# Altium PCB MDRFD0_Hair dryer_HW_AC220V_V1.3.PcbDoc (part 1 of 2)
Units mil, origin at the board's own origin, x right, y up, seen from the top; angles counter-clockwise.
Board outline 2501.37 x 2501.36 mil, 2 copper layers (Top Layer, Bottom Layer), stack 65.792 mil thick; 130 components, 77 nets, 332 pads, 233 vias.
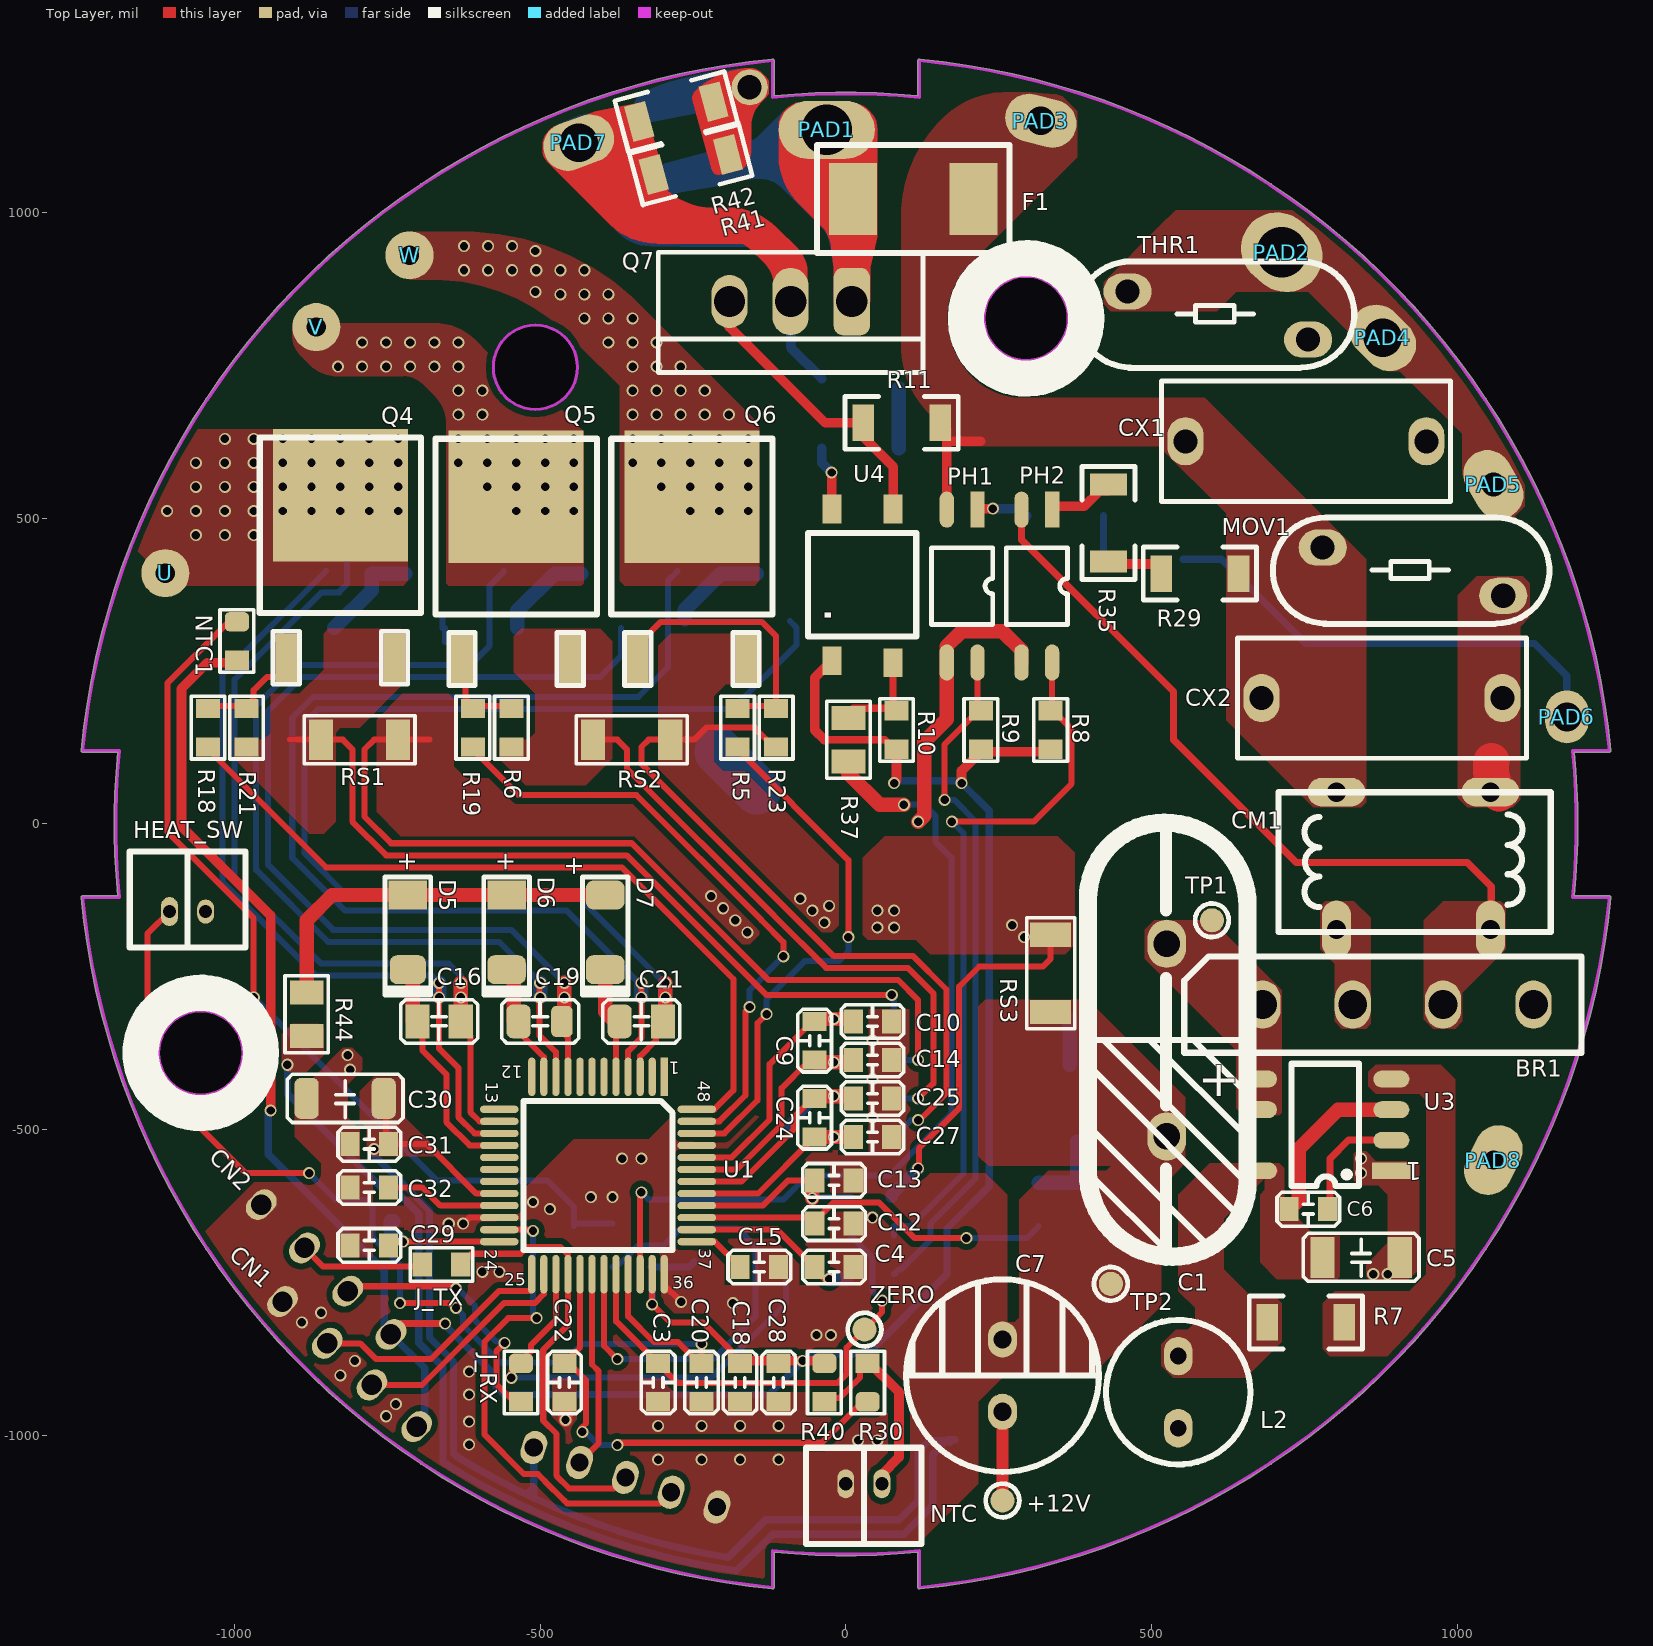
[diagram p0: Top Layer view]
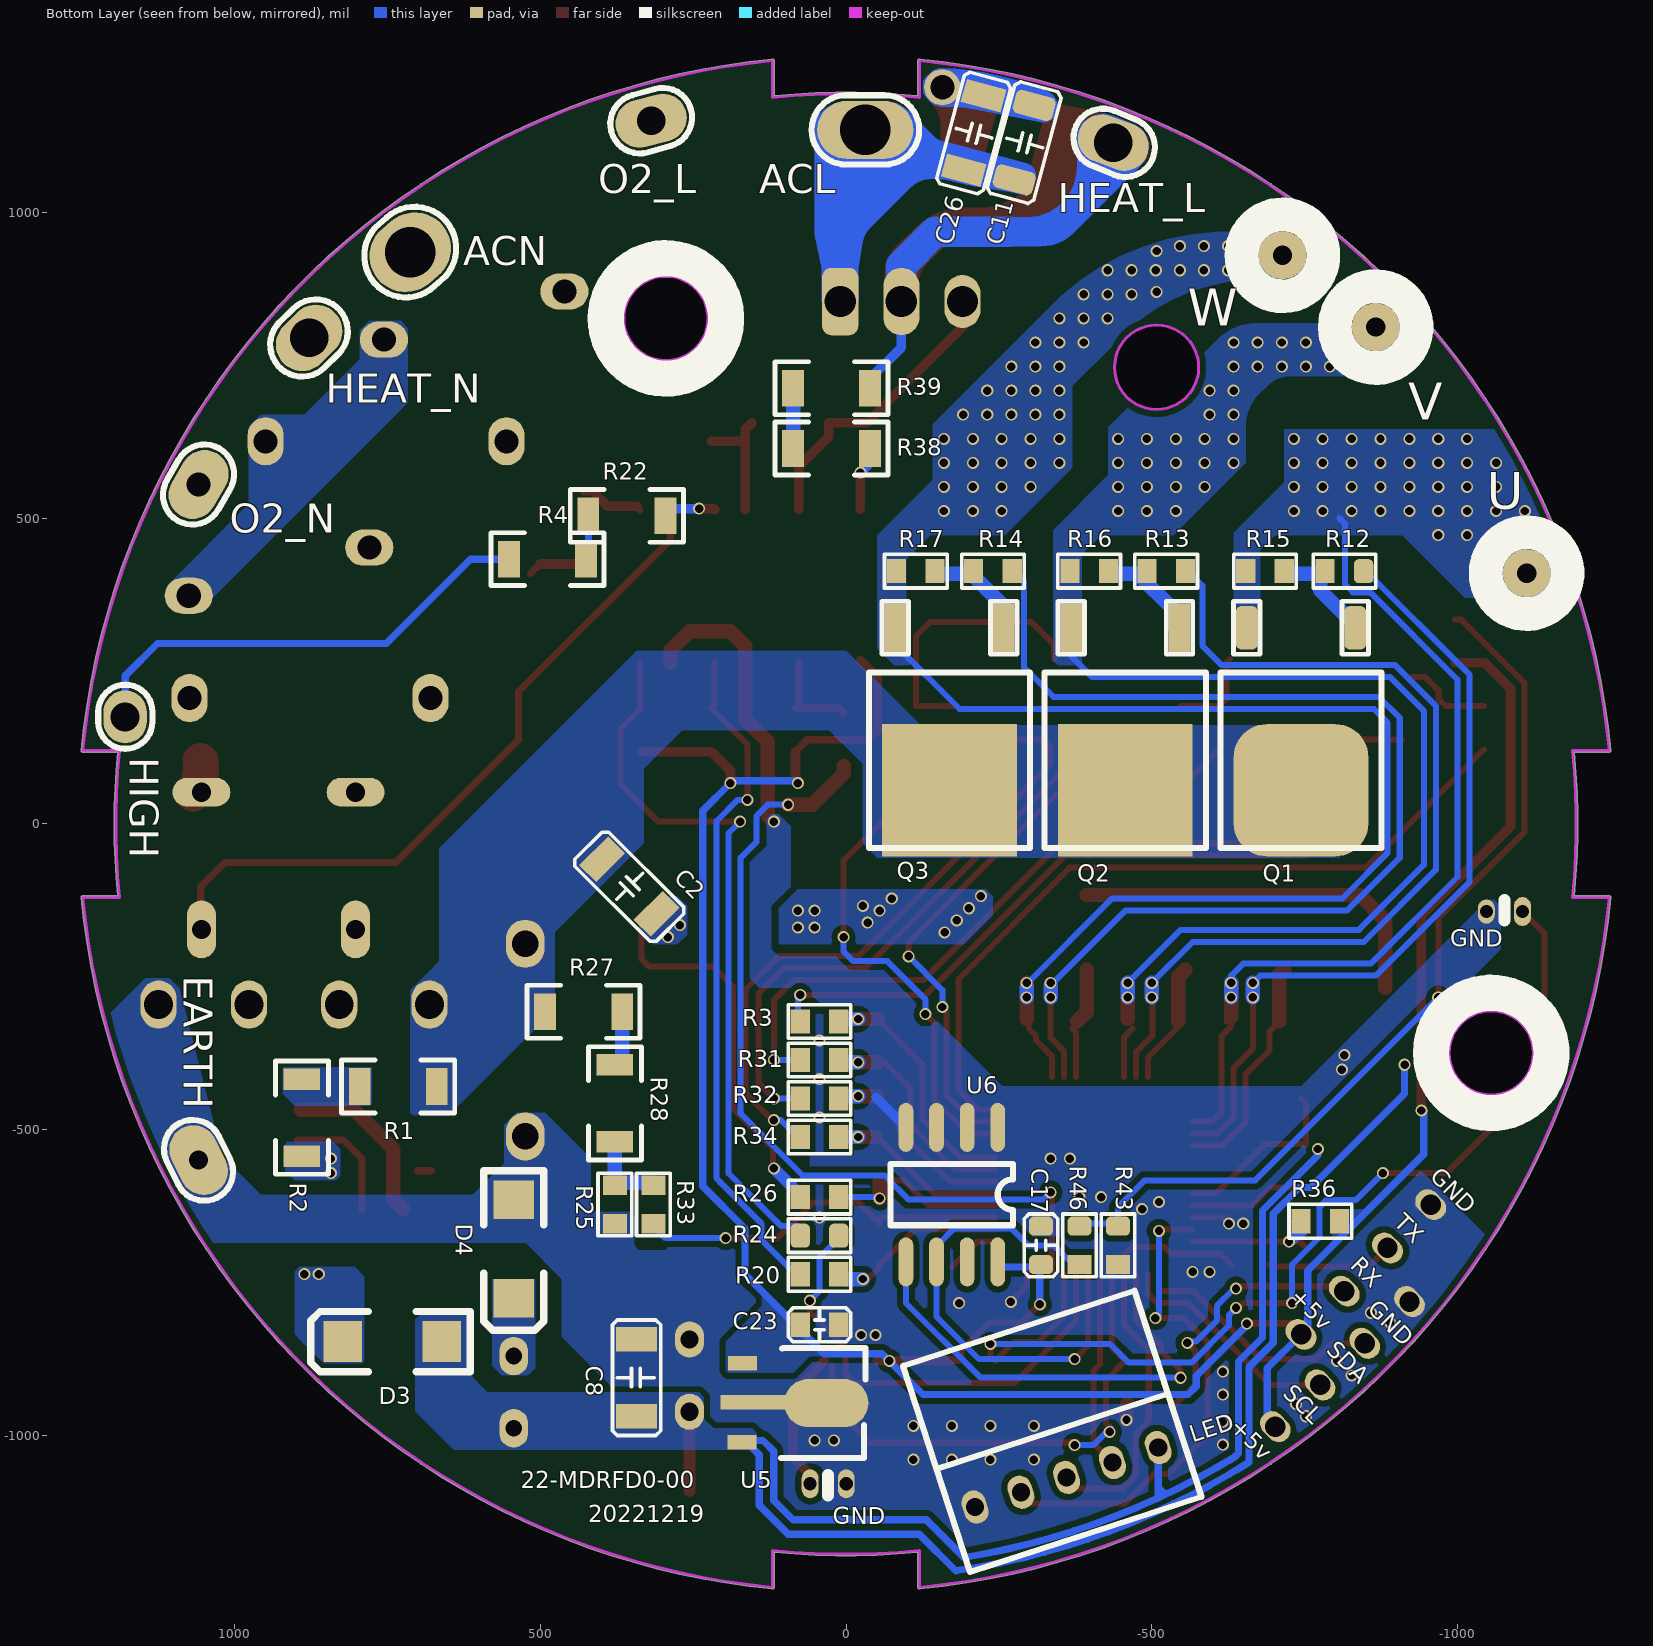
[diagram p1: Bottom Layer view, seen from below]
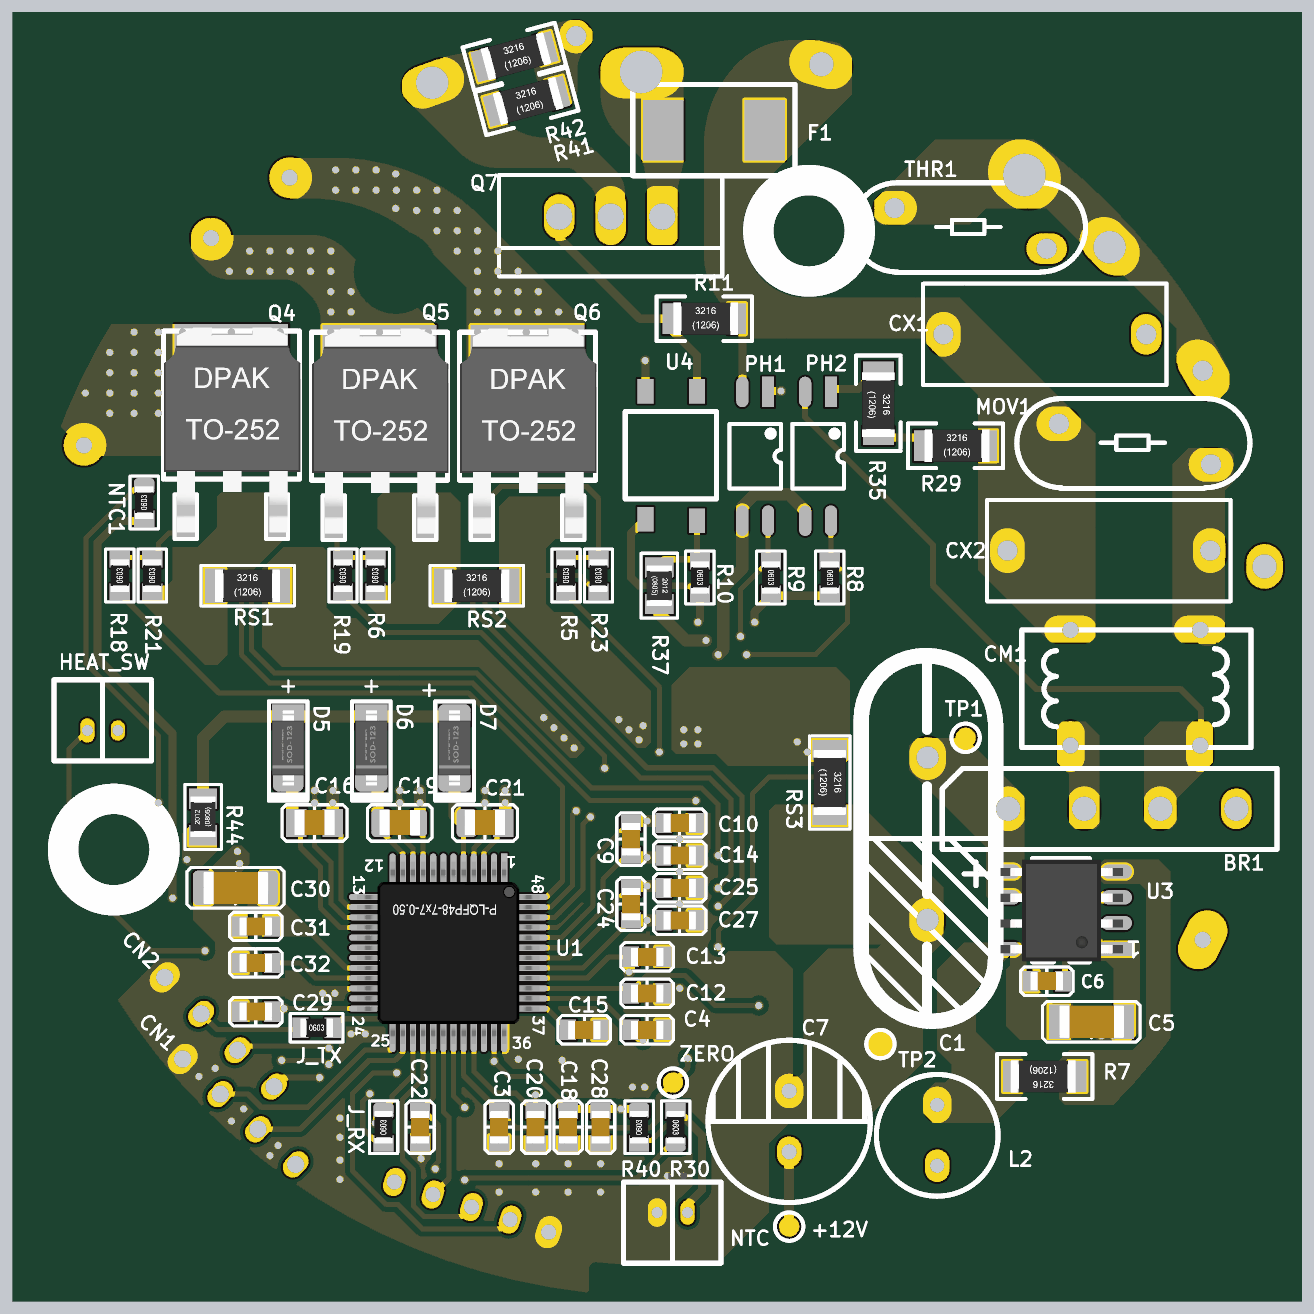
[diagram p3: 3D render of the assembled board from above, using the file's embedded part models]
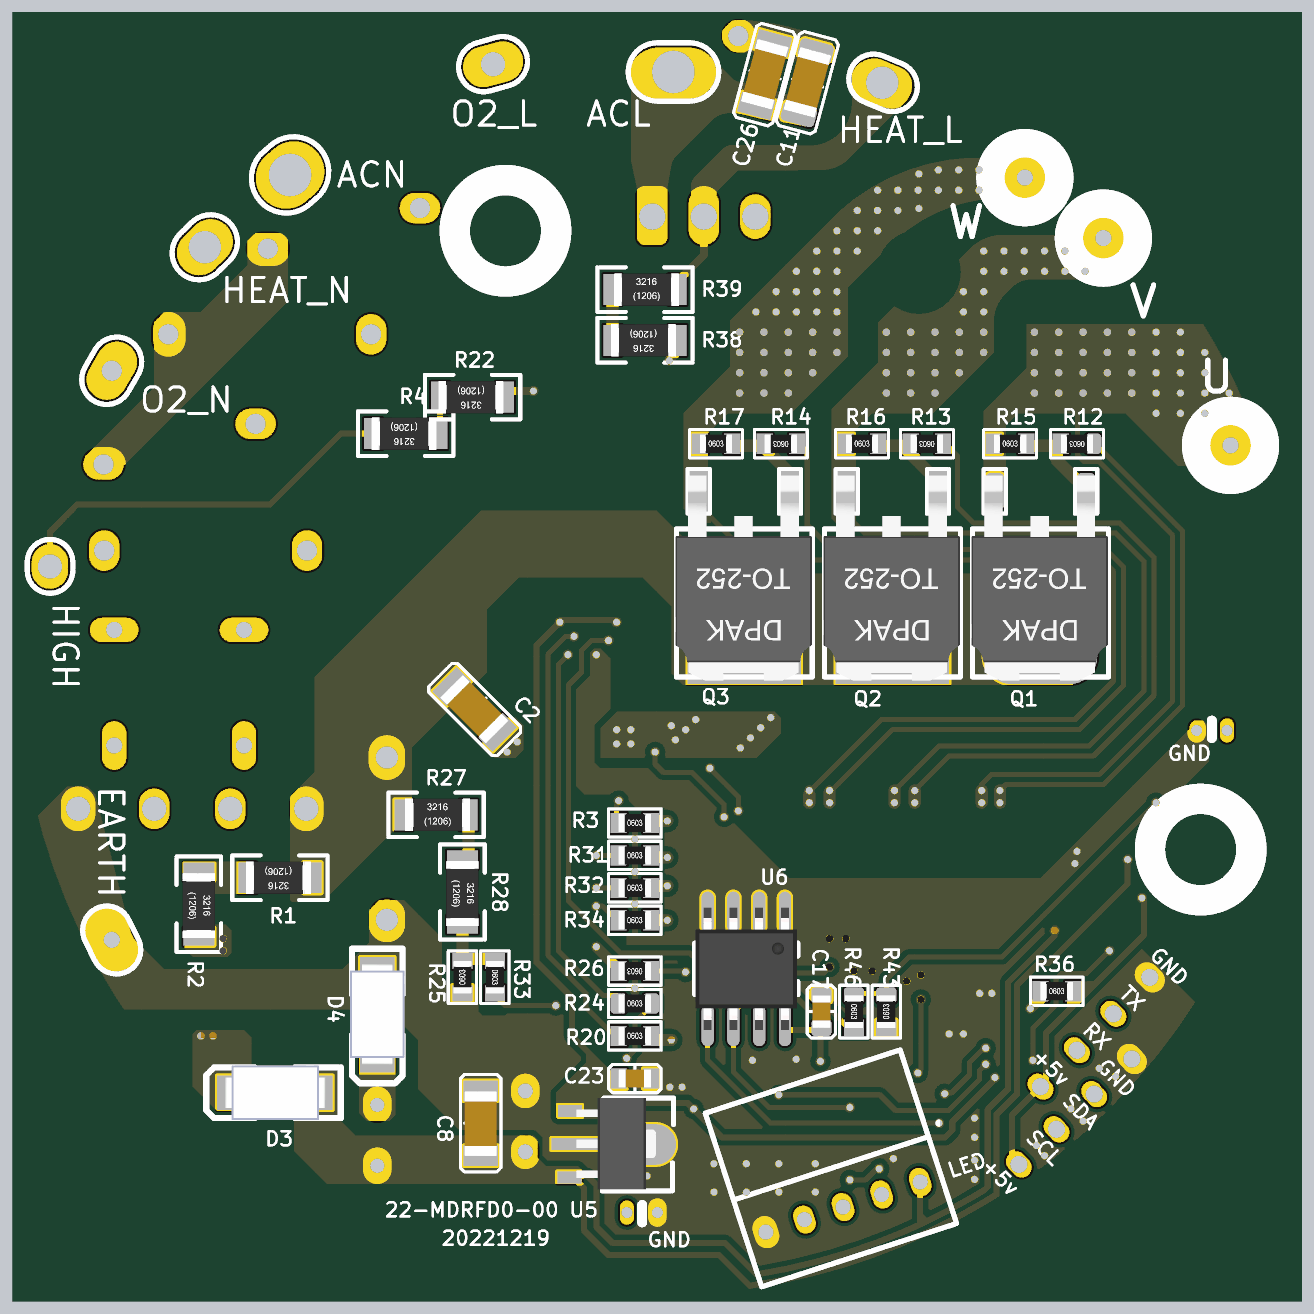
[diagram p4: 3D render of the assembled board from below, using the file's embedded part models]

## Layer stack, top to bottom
Top Solder: solder mask 0.4, Solder Resist, Dk 3.5
Top Layer: signal copper 1.4
Dielectric1: core 62.9921, FR-4, Dk 4.8
Bottom Layer: signal copper 1.4
Bottom Solder: solder mask 0.4, Solder Resist, Dk 3.5

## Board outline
-1250.68,-120.34 cw(c-1248.17,-120.1) -1247.89,-117.6 cw(c-1247.13,-120) -1247.13,-117.48 -1190.78,-117.48 cw(c0,0) -1190.78,117.49 -1247.13,117.49 cw(c-1247.13,120) -1247.87,117.6 cw(c-1248.17,120.1) -1250.68,120.34 cw(c0,0) -120.34,1250.67 cw(c-120.1,1248.17) -117.58,1248.17 cw(c-120.1,1248.17) -117.6,1247.88 cw(c-120,1247.14) -117.49,1247.14 -117.49,1190.78 cw(c0,0) 117.48,1190.78 117.48,1247.14 cw(c120,1247.14) 117.6,1247.88 cw(c120.1,1248.17) 120.34,1250.67 cw(c0,0) 1250.68,120.34 cw(c1248.17,120.1) 1250.69,120.1 cw(c1248.17,120.1) 1247.87,117.6 cw(c1247.13,120) 1247.13,117.49 1190.78,117.49 cw(c0,0) 1196.56,0 cw(c0,0) 1190.78,-117.48 1247.13,-117.48 cw(c1247.13,-120) 1247.89,-117.6 cw(c1248.17,-120.1) 1250.69,-120.1 cw(c1248.17,-120.1) 1250.68,-120.34 cw(c0,0) 120.34,-1250.68 cw(c120.1,-1248.17) 117.6,-1247.88 cw(c120,-1247.13) 117.48,-1247.13 117.48,-1190.78 cw(c0,0) -117.49,-1190.78 -117.49,-1247.13 cw(c-120,-1247.13) -117.6,-1247.88 cw(c-120.1,-1248.17) -117.58,-1248.17 cw(c-120.1,-1248.17) -120.34,-1250.68 cw(c0,0)
cut-out: -1124.02,-374.41 ccw(c-1055.12,-374.41) -1055.12,-443.31 ccw(c-1055.12,-374.41) -986.22,-374.41 ccw(c-1055.12,-374.41) -1055.12,-305.51 ccw(c-1055.12,-374.41)
cut-out: -576.77,746.85 ccw(c-507.87,746.85) -507.87,677.95 ccw(c-507.87,746.85) -438.98,746.85 ccw(c-507.87,746.85) -507.87,815.75 ccw(c-507.87,746.85)
cut-out: 225.59,826.77 ccw(c294.49,826.77) 294.49,757.87 ccw(c294.49,826.77) 363.38,826.77 ccw(c294.49,826.77) 294.49,895.67 ccw(c294.49,826.77)

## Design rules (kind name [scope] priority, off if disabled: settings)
Clearance Clearance_1 [InComponent('U1')] p1: gap=7.87
Clearance [All] p2: gap=9.84
ComponentClearance [All] p1 off: gap=10 collisioncheckmode=3 verticalgap=10 showdistances=FALSE
Height [All] p1 off: minheight=0 maxheight=1000 prefheight=500
HoleSize [All] p1: absolutevalues=TRUE maxlimit=236.22 minlimit=1 maxpercent=80.000 minpercent=20.000
HoleToHoleClearance [All] p1: gap=3.94 allowstackedmicrovias=TRUE
MinimumSolderMaskSliver [All] p1: minsoldermaskwidth=0
PolygonConnect [All] p1: connectstyle=Direct reliefconductorwidth=10 reliefentries=4 polygonreliefangle="90 Angle" airgapwidth=10
RoutingVias [All] p1: holewidth=28 width=50 viastyle="Through Hole" minholewidth=13.78 minwidth=19.68 maxholewidth=28 maxwidth=50
SilkToSilkClearance [All] p1: silktosilkclearance=0.39
SilkToSolderMaskClearance [IsPad] p1: minsilkscreentomaskgap=0 clearancetoexposedcopper=TRUE
SolderMaskExpansion SolderMaskExpansion_1 [IsVia] p1: expansion=-196.85
SolderMaskExpansion [All] p2: expansion=4
Width [All] p1: maxlimit=118.11 minlimit=9.84 preferedwidth=11.81
23 further rules are at their usual default settings.

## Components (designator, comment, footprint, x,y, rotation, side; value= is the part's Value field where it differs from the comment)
+12V "15V" 1MM 255.91,-1106.3 r0 top
BR1 "BR/UG4KB80" "DB KBP410" 809.06,-295.27 r0 top locked
C1 "150uF/400V" 33U400V 521.65,-198.82 r0 top locked
C2 "C/47nF/630V/1206" C1206#1 354.33,-102.36 r225 bottom
C3 "C/0.01uF/50V" C0603#1 -307.09,-913.39 r90 top
C4 "C/0.01uF/50V" C0603#1 -19.69,-724.41 r180 top
C5 "C/10uF/50V/1206" C1206#1 842.52,-708.66 r180 top
C6 "C/47nF/50V" C0603#1 755.91,-629.92 r0 top
C7 "100uF/35V" "CAPACITOR 8*13" 255.91,-961.1 r90 top locked
C8 "C/10uF/50V/1206" C1206#1 342.52,-905.51 r90 bottom
C9 "C/2nF/50V" C0603#1 -51.18,-354.33 r270 top
C10 "C/2nF/50V" C0603#1 43.31,-322.83 r0 top
C11 "NC" C1206#2 -291.34,1114.17 r285 bottom
C12 "C/0.1uF/50V" C0603#1 -19.68,-653.54 r180 top
C13 "C/2nF/50V" C0603#1 -19.68,-582.68 r0 top
C14 "C/2nF/50V" C0603#1 43.31,-385.83 r0 top
C15 "C/1uF/16V" C0603#1 -141.73,-724.41 r0 top
C16 "C/1uF/50V/0805" C0805#1 -665.35,-322.83 r0 top
C17 "C/0.1uF/50V" C0603#2 -318.9,-688.98 r270 bottom
C18 "C/0.1uF/16V" C0603#1 -173.23,-913.39 r270 top
C19 "C/1uF/50V/0805" C0805#2 -500,-322.83 r0 top
C20 "C/0.1uF/50V" C0603#1 -236.22,-913.39 r270 top
C21 "C/1uF/50V/0805" C0805#3 -334.65,-322.83 r0 top
C22 "C/0.1uF/50V" C0603#1 -460.63,-913.39 r270 top
C23 "C/10uF/25V" C0603#1 43.31,-818.9 r0 bottom
C24 "C/2nF/50V" C0603#1 -51.18,-480.31 r270 top
C25 "C/2nF/50V" C0603#1 43.31,-448.82 r0 top
C26 "NC" C1206#1 -208.66,1129.92 r285 bottom
C27 "C/2nF/50V" C0603#1 43.31,-511.81 r0 top
C28 "C/1uF/16V" C0603#1 -110.24,-913.39 r270 top
C29 "C/0.01uF/50V" C0603#1 -779.53,-688.98 r0 top
C30 "C/10uF/50V/1206" C1206#2 -818.9,-448.82 r180 top
C31 "C/0.1uF/50V" C0603#1 -779.53,-523.62 r180 top
C32 "C/0.1uF/50V" C0603#1 -779.53,-594.49 r180 top
CM1 "20mH/4A" 20mH 1054,52 r270 top
CN1 "PH-1*4/P2.54/180 NC" SIP4 -702.08,-985.54 r137 top locked
CN2 "PH-1*4/P2.54/180 NC" SIP4 -744.09,-834.65 r135 top
CX1 "0.22uF/275V/DIP" "CX 0.1UF" 545.43,625.79 r270 top
CX2 "0.22uF/275V/DIP" "CX 0.1UF" 669.84,205.94 r270 top
D3 "D/ES1J/SMA(DO-214AC)" "DIODE SMA" 661.42,-846.46 r0 bottom
D4 "D/ES1J/SMA(DO-214AC)" "DIODE SMA" 543.31,-614.17 r270 bottom
D5 "D/ES1006FL/SOD-123FL" SOD-123FL#1 -716.54,-177.17 r270 top
D6 "D/ES1006FL/SOD-123FL" SOD-123FL#2 -555.12,-177.17 r270 top
D7 "D/ES1006FL/SOD-123FL" SOD-123FL#3 -393.7,-177.17 r270 top
F1 "FUSE/3.5A/250V/6.1*2.6/SMD" "FUSE - 3.15A" 11.42,1022.05 r0 top
HEAT_SW "CON2/P1.5/180" CN2P#1 -1106.26,-143.19 r0 top locked
J_RX "R/0R NC" R0603#1 -531.5,-913.39 r90 top
J_TX "R/0R NC" R0603#2 -661.42,-720.47 r0 top
L2 "L/1mH/MCD-0608S-102MU-F-EV/DIP" L6*8 543.31,-870.08 r270 top
LED "CON5/P2.0/90" "CN5P  2.0MM" -360.79,-1068.39 r162 bottom locked
MOV1 "VDR/TVR10471KSY" "MOV 10D471K" 779.53,451.97 r0 top
NTC "CON2/P1.5/180" CN2P#2 58.66,-1079.02 r180 top
NTC1 "NTC/NCP18XV103J03RB/0603" R0603#1 -996.06,299.21 r90 top
PAD1 "ACL" 1.5MM#1 0,1334.64 r0 top
PAD2 "ACN" 1.5MM#2 909.45,1015.75 r0 top
PAD3 "O2L" 1.5MM#3 452.75,1291.34 r0 top
PAD4 "O2N" 1.5MM#4 1007.87,850.39 r0 top
PAD5 "HEAT_N" 1.5MM#5 1181.1,578.74 r0 top
PAD6 "SPEEDH" 1.5MM#6 1177.16,-594.49 r0 top
PAD7 "HEAT_L" 1.5MM#7 -145.67,1409.45 r0 top
PAD8 "EARTH" 1.5MM#8 1267.72,-586.62 r0 top
PH1 "IC/EL3H4A" SOP4(1.27MM) 215,514 r270 top
PH2 "IC/EL3H4A" SOP4(1.27MM) 337,514 r270 top
Q1 "MGM07N65/TO-252" TO-252#1 -842.52,291.34 r0 bottom
Q2 "MGM07N65/TO-252" TO-252#2 -555.12,291.34 r0 bottom
Q3 "MGM07N65/TO-252" TO-252#2 -267.72,291.34 r0 bottom
Q4 "MGM07N65/TO-252" TO-252#2 -925.2,301.43 r0 top
Q5 "MGM07N65/TO-252" TO-252#2 -637.8,299.21 r0 top
Q6 "MGM07N65/TO-252" TO-252#2 -350.39,299.21 r0 top
Q7 "BT139-800" MOS-LS -90.55,854.33 r90 top
R1 "R/510K/1206" 1206R 795.28,-429.13 r180 bottom
R2 "R/510K/1206" 1206R 889.76,-543.31 r90 bottom
R3 "R/1K" R0603#2 43.31,-322.83 r180 bottom
R4 "R/240K/1206" 1206R 551.18,433.07 r180 bottom
R5 "R/330R" R0603#2 -177.17,157.48 r90 top
R6 "R/10K/0603" R0603#2 -547.24,157.48 r90 top
R7 "R/3.3R/1206" 1206R 688.98,-814.96 r0 top
R8 "R/51K" R0603#2 334.65,153.74 r270 top
R9 "R/51K" R0603#2 220.47,153.74 r270 top
R10 "R/51K" R0603#2 82.68,153.74 r270 top
R11 "R/150R/1206" 1206R 154,656 r180 top
R12 "R/330R" R0603#3 -814.96,413.39 r0 bottom
R13 "R/330R" R0603#2 -523.62,413.39 r0 bottom
R14 "R/330R" R0603#2 -240.16,413.39 r0 bottom
R15 "R/10K/0603" R0603#2 -685.04,413.39 r180 bottom
R16 "R/10K/0603" R0603#2 -397.64,413.39 r180 bottom
R17 "R/10K/0603" R0603#2 -114.17,413.39 r180 bottom
R18 "R/330R" R0603#2 -1043.31,157.48 r90 top
R19 "R/330R" R0603#2 -610.24,157.48 r90 top
R20 "R/100R" R0603#2 43.31,-736.22 r180 bottom
R21 "R/10K/0603" R0603#2 -980.31,157.48 r90 top
R22 "R/240K/1206" 1206R 421.26,503.94 r180 bottom
R23 "R/10K/0603" R0603#2 -114.17,157.48 r90 top
R24 "R/100R" R0603#4 43.31,-673.23 r180 bottom
R25 "R/10K/0603" R0603#2 377.95,-622.05 r90 bottom
R26 "R/2K" R0603#2 43.31,-610.24 r0 bottom
R27 "R/470K/1206" 1206R 366.14,-307.09 r0 bottom
R28 "R/470K/1206" 1206R 377.95,-519.68 r90 bottom
R29 "R/240K/1206" 1206R 641.73,409.45 r180 top
R30 "R/1K/0603" R0603#1 35.43,-913.39 r270 top
R31 "R/1K" R0603#2 43.31,-385.83 r180 bottom
R32 "R/1K" R0603#2 43.31,-448.82 r180 bottom
R33 "R/2K" R0603#2 314.96,-622.05 r270 bottom
R34 "R/1K" R0603#2 43.31,-511.81 r180 bottom
R35 "R/240K/1206" 1206R 429.13,429.13 r90 top
R36 "R/10K/0603" R0603#2 -775.59,-649.61 r180 bottom
R37 "R/510R/0805" R0805 3.94,137.8 r270 top
R38 "R/22R/1206" 1206R 86.61,614.17 r180 bottom
R39 "R/22R/1206" 1206R -39.37,712.6 r0 bottom
R40 "R/10K/0603" R0603#1 -35.43,-913.39 r90 top
R41 "R/150R/1206" 1206R -192.91,1094.49 r195 top
R42 "R/150R/1206" 1206R -216.54,1181.1 r195 top
R43 "R/10K/0603" R0603#1 -444.88,-688.98 r90 bottom
R44 "R/10R/0805" R0805 -881.89,-311.02 r90 top
R46 "R/2K" R0603#3 -381.89,-688.98 r270 bottom
RS1 "R/0.1R/1W/1206" R1206 -795.28,137.8 r180 top
RS2 "R/0.1R/1W/1206" R1206 -350.39,137.8 r180 top
RS3 "R/0.1R/1W/1206" R1206 334.65,-244.09 r90 top
THR1 "NTC/SCK10054MSY/DIP" "MOV 10D471K" 460.43,870.79 r0 top
TP1 "HV" 1MM 598.43,-157.48 r0 top
TP2 "AGND" 1MM 433.07,-751.97 r0 top
U "U" 1.5MM#9 -1291.34,511.81 r90 top
U1 "MDRFD0AD48" LQFP-48 -405.51,-574.8 r270 top
U3 "IC/GR8903/SOP-7" SOP-7 783.46,-492.13 r180 top
U4 "IC/TLP265J" "SOP 4/TLP265J" -23,267 r90 top
U5 "T/APL78L05/SOT-89" SOT89-3 169.29,-881.89 r180 bottom
U6 "IC/24LC02/SOIC-8" "SOP 8" -248.03,-496.06 r270 bottom
V "V" 1.5MM#10 -944.88,1118.11 r90 top
W "W" 1.5MM#11 -1200.79,838.58 r90 top
ZERO "ZERO" 1MM 30.3,-826.77 r0 top

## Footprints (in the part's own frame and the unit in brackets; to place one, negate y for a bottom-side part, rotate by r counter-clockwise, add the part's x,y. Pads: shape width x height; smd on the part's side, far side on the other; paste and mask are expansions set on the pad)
1.5MM#1 [mm]
  oval 4x2.4 hole 2.1: 1(-0.8,-5.07)
1.5MM#2 [mm]
  oval 3.5x3 hole 2.1 rot 140: 1(-5,-2.05)
1.5MM#3 [mm]
  oval 3x2 hole 1.2 rot 165: 1(-3.41,-3.59)
1.5MM#4 [mm]
  oval 3x2.2 hole 1.6 rot 135: 1(-3.3,-1.41)
1.5MM#5 [mm]
  oval 3x2 hole 1 rot 120: 1(-3.11,-0.6)
1.5MM#6 [mm]
  oval 1.8x2.2 hole 1.2: 1(0.04,19.55)
1.5MM#7 [mm]
  oval 3x2 hole 1.6 rot 20: 1(-7.4,-7.5)
1.5MM#8 [mm]
  oval 3x2 hole 0.8 rot 64: 1(-5.31,0.94)
1.5MM#9 [mm]
  round 2 hole 0.8: 1(-2.58,-4.53)
1.5MM#10 [mm]
  round 2 hole 0.8: 1(-7.76,-2)
1.5MM#11 [mm]
  round 2 hole 0.8: 1(2.32,-12.37)
1MM [mm]
  round 1 smd paste-1: 1(0,0)
  silkscreen extent -0.7,-0.7 0.7,0.7
20mH [mm]
  oval 1.2x2.4 hole 0.8: 1(0,0) 4(0,-6.4)
  oval 2.4x1.2 hole 0.8: 2(5.7,0) 3(5.7,-6.4)
  silkscreen extent 0,-8.8 5.8,2.5
33U400V [mm]
  oval 1.6x2 hole 1.1: 1(0.076,0.076) 2(0.076,-7.924)
  silkscreen extent -3.2,-12.92 3.43,5.11
1206R [mm]
  rect 0.9x1.524 smd: 1(0,0) 2(3.2,0)
  silkscreen extent -0.75,-1.1 3.95,1.1, body extent -0.08,-0.8 3.12,0.8, height 0.55
C0603#1 [mm]
  rect 0.8x1 smd: 1(-0.8,0) 2(0.8,0)
  silkscreen extent -1.3,-0.7 1.3,0.7, body extent -0.8,-0.45 0.8,0.45, height 0.7
C0603#2 [mm]
  rrect50% 0.8x1 smd: 1(-0.8,0) 2(0.8,0)
  silkscreen extent -1.3,-0.7 1.3,0.7, body extent -0.8,-0.45 0.8,0.45, height 0.7
C0805#1 [mm]
  rect 1x1.4 smd: 1(-0.9,0) 2(0.9,0)
  silkscreen extent -1.6,-0.9 1.6,0.9, body extent -1,-0.6 1,0.65, height 1
C0805#2 [mm]
  rrect50% 1x1.4 smd: 1(-0.9,0)
  rrect50% 0.9x1.3 smd: 2(0.9,0)
  silkscreen extent -1.6,-0.9 1.6,0.9, body extent -1,-0.6 1,0.65, height 1
C0805#3 [mm]
  rrect50% 1x1.4 smd: 1(-0.9,0)
  rect 1x1.4 smd: 2(0.9,0)
  silkscreen extent -1.6,-0.9 1.6,0.9, body extent -1,-0.6 1,0.65, height 1
C1206#1 [mm]
  rect 1x1.7 smd: 1(-1.6,0) 2(1.6,0)
  silkscreen extent -2.4,-1 2.4,1, body extent -1.62,-0.8 1.58,0.8, height 1
C1206#2 [mm]
  rrect50% 1x1.7 smd: 1(-1.6,0) 2(1.6,0)
  silkscreen extent -2.4,-1 2.4,1, body extent -1.62,-0.8 1.58,0.8, height 1
"CAPACITOR 8*13" [mm] "¹q®e,¶¡¶Z2.5mm,ª½®"
  oval 1.5x1.2 hole 0.75: 1(0,0) 2(3,0)
  silkscreen extent -2.5,-4 5.5,4
CN2P#1 [mm]
  oval 0.7x1.2 hole 0.55: 1(0,0)
  oval 0.7x1 hole 0.55: 2(1.5,0)
  silkscreen extent -1.65,-1.5 3.15,2.5
CN2P#2 [mm]
  oval 0.7x1.2 hole 0.55: 1(0,0) 2(1.5,0)
  silkscreen extent -1.65,-1.5 3.15,2.5
"CN5P  2.0MM" [mm]
  oval 1x1.4 hole 0.75: 1(-4,0) 2(-2,0) 3(0,0) 4(2,0) 5(4,0)
  silkscreen extent -5.03,-2.5 5.08,6.5
"CX 0.1UF" [mm] "¹q®e,¶¡¶Z15mm¼e9mmªø18.2mm"
  oval 2x1.5 hole 1: 1(0,0.25) 2(0,10.25)
  silkscreen extent -2.5,-0.75 2.5,11.25
"DB KBP410" [mm]
  oval 1.5x2 hole 1.2: 1(-3.25,0) 2(0.5,0) 3(4.25,0) 4(8,0)
  silkscreen extent -6.5,-2 10,1.99
"DIODE SMA" [mm]
  rect 1.6x1.7 smd: 1(0,0) 2(4.1,0)
  silkscreen extent -1.2,-1.25 5.43,1.25, body extent -0.47,-1.35 4.53,1.35, height 2.15
"FUSE - 3.15A" [mm] "港柬,SET-T3.15A,250V,3.15A,8.5mm*4mm*8.5mm,Pitch:5.08mm,DIP,SET Slow Blow Fuse"
  rect 2x3 smd: 1(0,0) 2(5,0)
  silkscreen extent -1.5,-2.24 6.5,2.25
L6*8 [mm] "MAG.LAYERS,MCD-0608S-102MU-F-EV,1mH,0.25A,£r8mm*10mm,DIP"
  oval 1.6x1.2 hole 0.7: 1(0,0) 2(3,0)
  silkscreen extent -1.5,-3 4.5,3
LQFP-48 [mm]
  rect 1.6x0.3 smd: 1(-4.1,2.75)
  oval 1.6x0.3 smd: 2(-4.1,2.25) 3(-4.1,1.75) 4(-4.1,1.25) 5(-4.1,0.75) 6(-4.1,0.25) 7(-4.1,-0.25) 8(-4.1,-0.75) 9(-4.1,-1.25) 10(-4.1,-1.75) 11(-4.1,-2.25) 12(-4.1,-2.75) 25(4.1,-2.75) 26(4.1,-2.25) 27(4.1,-1.75) 28(4.1,-1.25) 29(4.1,-0.75) 30(4.1,-0.25) 31(4.1,0.25) 32(4.1,0.75) 33(4.1,1.25) 34(4.1,1.75) 35(4.1,2.25) 36(4.1,2.75)
  oval 0.3x1.6 smd: 13(-2.75,-4.1) 14(-2.25,-4.1) 15(-1.75,-4.1) 16(-1.25,-4.1) 17(-0.75,-4.1) 18(-0.25,-4.1) 19(0.25,-4.1) 20(0.75,-4.1) 21(1.25,-4.1) 22(1.75,-4.1) 23(2.25,-4.1) 24(2.75,-4.1) 37(2.75,4.1) 38(2.25,4.1) 39(1.75,4.1) 40(1.25,4.1) 41(0.75,4.1) 42(0.25,4.1) 43(-0.25,4.1) 44(-0.75,4.1) 45(-1.25,4.1) 46(-1.75,4.1) 47(-2.25,4.1) 48(-2.75,4.1)
  round 0.5 on Top Overlay: ""(-2.4,2.4)
  silkscreen extent -3.1,-3.1 3.1,3.1, body extent -4.5,-4.5 4.5,4.5, height 1.45
MOS-LS [mm]
  rrect50% 2.8x1.5 hole 1.3: 1(0,-2.54)
  oval 2.8x1.5 hole 1.3: 2(0,0)
  oval 2.2x1.5 hole 1.3: 3(0,2.54)
  silkscreen extent -2.95,-5.5 2.05,5.5
"MOV 10D471K" [mm] "VDR,¶¡¶Z7.5mmª½®"
  oval 2x1.5 hole 1: 1(0,0) 2(7.5,-2)
  silkscreen extent -2.07,-3.18 9.42,1.25
R0603#1 [mm]
  rect 0.8x1 smd: 1(-0.8,0)
  rrect50% 0.8x1 smd: 2(0.8,0)
  silkscreen extent -1.3,-0.7 1.3,0.7, body extent -0.8,-0.45 0.8,0.45, height 0.5
R0603#2 [mm]
  rect 0.8x1 smd: 1(-0.8,0) 2(0.8,0)
  silkscreen extent -1.3,-0.7 1.3,0.7, body extent -0.8,-0.45 0.8,0.45, height 0.5
R0603#3 [mm]
  rrect50% 0.8x1 smd: 1(-0.8,0)
  rect 0.8x1 smd: 2(0.8,0)
  silkscreen extent -1.3,-0.7 1.3,0.7, body extent -0.8,-0.45 0.8,0.45, height 0.5
R0603#4 [mm]
  rrect50% 0.8x1 smd: 1(-0.8,0) 2(0.8,0)
  silkscreen extent -1.3,-0.7 1.3,0.7, body extent -0.8,-0.45 0.8,0.45, height 0.5
R0805 [mm]
  rect 1x1.4 smd: 1(-0.9,0) 2(0.9,0)
  silkscreen extent -1.6,-0.9 1.6,0.9, body extent -1,-0.62 1,0.63, height 0.45
R1206 [mm]
  rect 1x1.7 smd: 1(-1.6,0) 2(1.6,0)
  silkscreen extent -2.3,-1 2.3,1, body extent -1.6,-0.8 1.6,0.8, height 0.55
SIP4 [mm]
  oval 1x1.4 hole 0.85: 1(0,0) 2(2.54,0) 3(5.08,0) 4(7.62,0)
SOD-123FL#1 [mm]
  rect 1.2x1.6 smd: 1(-1.55,0)
  rrect50% 1.2x1.5 smd: 2(1.55,0)
  silkscreen extent -2.3,-0.98 2.6,0.95, body extent -1.85,-0.8 1.85,0.8, height 1.25
SOD-123FL#2 [mm]
  rect 1.2x1.6 smd: 1(-1.55,0)
  rrect50% 1.2x1.6 smd: 2(1.55,0)
  silkscreen extent -2.3,-0.98 2.6,0.95, body extent -1.85,-0.8 1.85,0.8, height 1.25
SOD-123FL#3 [mm]
  rrect50% 1.2x1.6 smd: 1(-1.55,0) 2(1.55,0)
  silkscreen extent -2.3,-0.98 2.6,0.95, body extent -1.85,-0.8 1.85,0.8, height 1.25
SOP4(1.27MM) [mm]
  rect 1.5x0.6 smd: 1(0,0)
  oval 1.5x0.6 smd: 2(0,-1.27) 3(6.35,-1.27) 4(6.35,0)
  silkscreen extent 1.59,-1.9 4.77,0.64
"SOP 4/TLP265J" [mm]
  rect 1.2x0.8 smd: 1(0,0) 3(-0.085,-2.54) 4(6.3,-2.54) 6(6.3,0)
  silkscreen extent 1,-3.5 5.3,1
"SOP 8" [mil]
  oval 80x24 smd: 1(0,0) 2(0,-50) 3(0,-100) 4(0,-150) 5(220,-150) 6(220,-100) 7(220,-50) 8(220,0)
  silkscreen extent 60,-175 160,25, body extent -9,-174 229,24, height 63
SOP-7 [mm]
  rect 1.6x0.7 smd: 1(-2.75,1.905)
  oval 1.5x0.7 smd: 2(-2.75,0.635) 3(-2.75,-0.635) 4(-2.75,-1.905) 5(2.75,-1.905) 6(2.75,-0.635) 8(2.75,1.905)
  silkscreen extent -1.4,-2.54 1.4,2.54, body extent -3.05,-2.49 2.99,2.53, height 1.6
SOT89-3 [mil]
  rect 47.24x23.62 smd: 1(0,0) 3(-1,-129)
  rect 118.11x23.62 smd: 2(23,-64)
  oval 137.79x78.74 smd: 2(137,-65)
  silkscreen extent 63,-155 201,25, body extent 13,-152 167,25, height 55
TO-252#1 [mm]
  rrect50% 0.9x1.8 smd: 1(0.25,-0.75) 3(4.75,-0.75)
  rrect50% 5.6x5.5 smd: 2(2.5,6)
  silkscreen extent -0.85,-1.85 5.85,8.4, body extent -0.83,-1.53 5.91,8.57, height 2.37
TO-252#2 [mm]
  rect 0.9x2 smd: 1(0.25,-0.75) 3(4.75,-0.75)
  rect 5.6x5.5 smd: 2(2.5,6)
  silkscreen extent -0.85,-1.85 5.85,8.4, body extent -0.83,-1.53 5.91,8.57, height 2.37

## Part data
+12V TP1 TP2 ZERO: library part TESTPOINT, "TESTPOINT"
BR1: "UG4KB80,4A,800V,10.8*13.8mm(L*W),GULFSEMI, DIP,³Í®¦³Ç"
C1: library part C/E/150uF/400V/18*40, "N.C.C,KXJ,150uF,400V,¡Ó20%,P:7.5*18*40,DIP,105¢J"
C2: "TDK,47nF,630V,∮10%,1206"
C3 C4 C29: "PSA,0603B103K500,0.01uF(103)(10n),50V,∮10%,X7R,0603,SMD"
C5 C8 C30: "PSA,1206X106K500CT,10uF,50V,∮20%,X5R,1206,SMD"
C6: library part C/0.1uF/50V, "0.1uF(104)(100n),50V,∮10%,X7R,0603,PSA"
C7: library part C/E/100uF/35V/6.3*11, "100uF,35V,£r6,6.3*11"
C9 C10 C14 C24 C25 C27: library part C/2nF/16V, "2nF/50V/∮15%/X7R,0603,PSA"
C11 C26: library part C/0.22uF/100V/1206
C12 C17 C20 C22 C31 C32: "0.1uF(104)(100n),50V,∮10%,X7R,0603,PSA"
C13: "2nF/50V/∮15%/X7R,0603,PSA"
C15 C28: "1uF(105),16V,¡Ó10%,X7R,0603,PSA,¥@·R"
C16 C19 C21: "1uF(105)(1000n) ,  50V , -20+80% , X7R , 0805,¥@·R"
C18: "0.1uF(104)(100n),16V,∮10%,X7R,0603,PSA"
C23: "´¹¤ù¹q®e 10uF(106),25V,+/-10%,X5R,0603,¥@·R"
CM1: library part GM
CN1 CN2: library part PH-1*4/P2.54/180, "CHERNG WEEI,P101-SGP-100/030-4,Pitch:2.54mm,4Pin,180«×,L:10.16mm*W:2.54mm*H:10mm,Header,PBT"
CX1 CX2: library part C/X/0.22uF/275V/DIP, "ª÷ÄÝ¤Æ¶ì½¦AC¹q®e PXK , 0.22uF(224) , 275V , Class X2 , AC/¡Ó10% , 18*9.5*15.5(L*T*H) , Pitch¡G15;MKP,0.22uF(224),275V,Class X2,AC/¡Ó10%,L:18mm*D:8mm*H:13mm,Pitch:15mm,HUA JUNG"
D3 D4: "PANJIT,ES1J ,600V,1A,DO-214AC,SMD"
D5 D6 D7: "ES1006FL,SOD-123FL"
F1: library part FUSE/3.15A/250V/4*8.5/DIP, "3.5A,250V,6.1mm*2.6mm(2410)"
HEAT_SW NTC: "Header 180«×,CP-W15-02,Pitch:1.5mm,2Pin,©Ó¬¨"
J_RX J_TX: library part R/0R, "´¹¤ù¹qªý  0R , 1% , 0603,¥@·R"
L2: "MAG.LAYERS,MCD-0608S-102MU-F-EV,1mH,0.25A,£r8mm*10mm,DIP"
LED: "TKP,P110L-05,P:2.0,5Pin,90«×,12*7.6*4.6,DIP"
MOV1: "TKS,TVR10471KSY,470V,¡Ó10%,£r10mm,D:12.5mm,Pitch:7.5mm,DIP"
NTC1: "Murata,NCP18XV103J03RB,10K£[,£]:3900,0.31mA(25¢XC),100mW,SMD,0603,-40¢XC~+125¢XC"
PAD1 PAD2 PAD3 PAD4 PAD5 PAD6 PAD7 PAD8 U V W: library part PAD/WELDING, "WELDING"
PH1 PH2: "EVERLIGHT,EL3H4A,4Pin,SMD,AC Input Photocoupler,1mA(IF),5V(VCE)"
Q1 Q2 Q3 Q4 Q5 Q6: library part T/EM07N65/TO-252, "EnergicTek,EM07N65,650V,7A,1.4£[,TO-252,SMD,N-Channel Fast Switching MOSFET"
Q7: library part Triac, "Silicon Bidirectional Triode Thyristor"
R1 R2: "510K/1206"
R3 R30 R31 R32 R34: "1K,1%,0603,PSA"
R4 R22 R29 R35: "240K,5%,1206"
R5 R12 R13 R14 R18 R19: "330R,1%,0603¡A¥@·R"
R6 R15 R16 R17 R21 R23 R25 R36 R40 R43: "PSA,WR06X1002FTL,10K£[,0603,SMD"
R7: "3.3R,1%,1206,PSA"
R8 R9 R10: "51K,1%,0603,PSA"
R11 R41 R42: "150R,1%,1206,PSA"
R20 R24: "100R,1%,0603,PSA,¥@·R"
R26 R33: "2K,5%,0603,PSA,¥@·R"
R27 R28: "470K,1%,1206,PSA"
R37: "510R,1%,0805,PSA"
R38 R39: "22R,1%,1206,PSA(¥@·R)"
R44: "PSA,WR08X10R0FTL,10R,0805,SMD"
R46: "2K,1%,0603,PSA,¥@·R"
RS1 RS2 RS3: library part R/150R/1206, "150R,1%,1206,PSA"
THR1: "THINKING,SCK10054MSY,5R,4A,£r10mm,P:5mm,DIP"
U1: library part IC/ET1271B/LQFP-48
U3: "Grenergy,GR8903AKAG,SOP-7,SMD,Vo=15V,Iomax=0.25A"
U4: "TOSHIBA,TLP265J,4Pin,SMD,Photocouplers,10mA(IF),600V"
U5: "APL78L05"
U6: "MicroChip,24LC02BT-I/SN,2K,8PIN,I2C/SOIC-8,EEPROM,SMD"

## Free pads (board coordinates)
  round 23.62 on Top Overlay: 0(344,433) 1(220,433)
  round 59.06 hole 39.37: 2(-157.48,1204.72)

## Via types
v1: diameter 19.68, hole 13.78, Top Layer to Bottom Layer, tented both sides, 233 vias

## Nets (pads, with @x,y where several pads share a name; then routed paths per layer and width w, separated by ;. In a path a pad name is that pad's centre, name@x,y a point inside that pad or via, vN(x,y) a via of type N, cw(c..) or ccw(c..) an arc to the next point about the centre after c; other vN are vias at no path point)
+5V: C17.2 C18.1 C23.2 C28.1 CN1.1 CN2.1 NTC1.1 R8.2 R9.2 R10.2 R36.2 R40.2 U1.35 U4.1 U5.1 U6.8 | length 4511.5
  Top Layer w9.84: U1.35@-316.93,-736.22 v1(-316.93,-785.43) -287.4,-814.96 -234.07,-814.96 -188.98,-860.06 -188.98,-874.02 -185.04,-877.95 C18.1@-173.23,-877.95
  Top Layer w11.81: CN2.1@-744.09,-834.65 -726.42,-816.97 v1(-655.54,-816.97) ; -35.43,137.8 63.19,137.8 R10.2@82.68,118.31
  Top Layer w15.75: NTC1.1@-996.06,263.78 -1044.29,263.78 -1086.61,221.46 -1086.61,-3.94 -940.94,-149.61 v1(-940.94,-468.5) ; C18.1@-173.23,-877.95 R40.2@-51.18,-877.95 ; -35.43,137.8 -51.18,153.54 -51.18,238.82 U4.1@-23,267 ; v1(78.74,66.93) 82.68,70.87 R10.2@82.68,118.31 ; v1(188.98,66.93) 188.98,86.81 220.47,118.31 R8.2@334.65,118.31
  Bottom Layer w11.81: v1@-944.88,-468.5 -944.88,-540.13 -754.92,-730.09 -754.92,-823.82 CN2.1@-744.09,-834.65 -688.98,-889.76 -688.98,-972.44 CN1.1@-702.08,-985.54 ; v1(-655.54,-816.97) -655.54,-819.83 -572.83,-902.54 -572.83,-919.29 -559.06,-933.07 -125.98,-933.07 v1(-70.87,-877.95) -59.06,-866.14 35.43,-866.14 165.35,-736.22 165.35,-661.42 234.25,-592.52 234.25,21.65 v1(188.98,66.93) 185.04,70.87 82.68,70.87 v1(78.74,66.93) ; v1(-316.93,-785.43) -316.93,-726.38 -318.9,-724.41 -256.38,-724.41 U6.8@-248.03,-716.06
+12V: +12V.1 C7.1 C8.1 C30.1 C31.1 D3.1 L2.2 LED.5 R44.1 U1.20 U5.3 | length 3854.3
  Top Layer w9.84: C30.1@-744.09,-448.82 -751.97,-456.69 -751.97,-523.62 C31.1@-748.03,-523.62 -685.04,-523.62 -604.33,-604.33 U1.20@-566.93,-604.33
  Top Layer w19.68: +12V.1@255.9,-1090.55 C7.1@255.9,-961.1
  Bottom Layer w11.81: v1(-913.39,-393.7) -913.39,-440.94 -759.84,-594.49 -741.51,-594.49 -698.82,-637.18 -698.82,-848.43 -658.78,-888.46 -658.78,-1043.73 ; v1(-771.65,-531.5) -771.65,-541.64 -681.13,-632.15 -681.13,-839.53 -641.73,-878.94 -641.73,-1028.96 -635.89,-1034.8 ; -640.47,-1055.07 cw(c0,0) -658.78,-1043.74 ; -617.73,-1045.74 cw(c0,0) -635.89,-1034.8 ; LED.5@-510.57,-1019.72 -510.57,-1100.72 -511.47,-1101.62 ; -195.42,-1198.74 ccw(c0,0) -192.66,-1199.19 ; -181.16,-1220.88 cw(c0,0) -658.78,-1043.74 ; -179.95,-1221.63 -119.74,-1161.42 94.49,-1161.42 141.73,-1114.17 141.73,-1031.5 U5.3@165.16,-1008.07 ; U5.3@170.29,-1010.89 167.47,-1008.07 U5.3@165.16,-1008.07 ; U5.3@178,-1006.95 166.28,-1006.95 U5.3@165.16,-1008.07 ; -635.89,-1034.8 ccw(c0,0) -511.47,-1101.62 ; -511.47,-1101.62 ccw(c0,0) -192.66,-1199.19 ; -192.66,-1199.19 -131.26,-1137.8 86.61,-1137.8 118.11,-1106.3 118.11,-1025.59 135.63,-1008.07 U5.3@165.16,-1008.07
ACL: C11.2 C26.2 F1.1 PAD1.1 Q7.1
ACL1: CM1.4 CX1.1 CX2.1 F1.2 MOV1.1 PAD3.1 PH1.2 R11.1 R29.1 | length 202
  Top Layer w15.75: R11.1@154,656 165,645 165,625.98 ; PH1.2@165,514 165,625.98 ; 220.47,625.98 165,625.98
ACN: PAD2.1 PAD4.1 PAD5.1 THR1.1
ACN1: BR1.3 CM1.2 PH2.2 | length 1187.2
  Top Layer w11.81: PH2.2@287,514 287,464.97 535.43,216.54 535.43,137.8 736.22,-62.99 1015.75,-62.99 1055.12,-102.36 1055.12,-182.57 CM1.2@1048.97,-188.72
AGND: BR1.4 C1.2 C3.1 C4.1 C7.2 C8.2 C10.2 C12.1 C13.2 C14.2 C15.2 C17.1 C18.2 C20.2 C22.2 C23.1 C25.2 C27.2 C28.2 C29.1 C30.2 C31.2 C32.2 CN1.4 CN2.4 D4.1 HEAT_SW.2 LED.1 NTC.2 PAD8.1 PH1.3 PH2.3 R25.1 R43.1 RS3.1 TP2.1 U1.22 U1.36 U1.45 U5.2 U6.1 U6.2 U6.3 U6.4 | length 729.1
  Top Layer w9.84: v1(-625.98,-653.54) -616.14,-643.7 U1.22@-566.93,-643.7 ; U1.36@-297.24,-736.22 -296.26,-737.21 -296.26,-754.92 v1(-269.69,-781.5)
  Top Layer w15.75: CN2.4@-956.23,-622.51 CN2.4@-948.82,-629.92
  Top Layer w23.62: C22.2@-460.63,-948.82 -458.66,-950.79 v1(-458.66,-974.41) ; v1(118.11,3.94) 127.95,13.78 127.95,134.24 165,171.28 PH1.3@165,264 165,290.98 189.2,315.18 255.69,315.18 287,283.87 PH2.3@287,264
  Bottom Layer w15.75: CN2.4@-956.23,-622.51 -937.47,-622.51 CN2.4@-946.85,-613.14 ; U6.4@-98.03,-496.06 -49.21,-447.24
  other v1: -307.09,-1039.37 -236.22,-1039.37 -173.23,-1039.37 -110.24,-1039.37 -616.14,-1014.76 19.68,-1007.87 51.18,-1007.87 -307.09,-984.25 -236.22,-984.25 -173.23,-984.25 -110.24,-984.25 -616.14,-977.36 -751.97,-968.5 -736.22,-948.82 -616.14,-933.07 -826.77,-901.57 -616.14,-895.67 -803.15,-877.95 -48.23,-835.63 -24.61,-835.63 -889.76,-814.96 -858.27,-799.21 -185.04,-783.46 -594.49,-732.28 -566.93,-732.28 -649.61,-653.54 43.31,-643.7 -484.25,-629.92 -511.81,-618.11 -417.32,-610.24 -381.89,-610.24 -366.14,-547.24 -334.65,-547.24 43.31,-480.31 43.31,-417.32 -811.02,-401.57 -814.96,-377.95 43.31,-354.33
AOCP: C13.1 R26.1 U1.40 | length 299.4
  Top Layer w9.84: U1.40@-244.09,-624.02 -135.83,-624.02 -94.49,-582.68 C13.1@-55.12,-582.68
  Top Layer w23.62: v1(-55.12,-612.2) C13.1@-55.12,-582.68
  Bottom Layer w9.84: v1(-55.12,-612.2) -53.15,-610.24 R26.1@7.87,-610.24
COM: C2.2 Q6.3 R23.1 R26.2 R31.1 R34.1 RS1.1 RS2.1 RS3.2 | length 3199.7
  Top Layer w9.84: -681.1,137.8 -771.65,137.8 -787.4,122.05 -787.4,12.09 -743.81,-31.5 -350.39,-31.5 -126.97,-254.92 85,-254.92 118.11,-288.04 v1(118.11,-385.83) ; R23.1@-114.17,122.05 -149.61,157.48 -228.35,157.48 -248.03,137.8 -322.83,137.8 -334.65,125.98 -334.65,98.43 -20.67,-215.55 109.25,-215.55 164.37,-270.67 164.37,-440.14 120.26,-484.25 v1(118.11,-484.25) ; v1@119.09,-562.99 119.09,-530.51 185.04,-464.57 185.04,-265.75 217.52,-233.27 321.85,-233.27 334.65,-220.47 RS3.2@334.65,-181.11
  Bottom Layer w9.84: R34.1@78.74,-511.81 106.3,-484.25 v1(118.11,-484.25) ; R31.1@78.74,-385.83 v1(118.11,-385.83)
  Bottom Layer w19.68: R26.2@74.8,-610.24 74.8,-606.3 v1(118.11,-562.99)
  other v1: 291.34,-185.04 -161.42,-177.17 51.18,-169.29 78.74,-169.29 271.65,-165.35 -35.43,-161.42 -181.1,-157.48 -55.12,-141.73 51.18,-141.73 78.74,-141.73 -200.79,-137.8 -27.56,-133.86 -74.8,-122.05 -220.47,-118.11
CS: R7.2 U3.4
HEAT: R37.2 U1.34 | length 1385.2
  Top Layer w9.84: U1.34@-336.61,-736.22 -336.61,-604.33 v1(-334.65,-602.36)
  Top Layer w23.62: R37.2@3.94,94.49 3.94,82.68 55.12,31.5 v1(94.49,31.5)
  Bottom Layer w9.84: v1(-334.65,-602.36) -322.83,-614.17 -102.36,-614.17 -62.99,-574.8 70.87,-574.8 172.24,-473.43 172.24,-55.12 146.65,-29.53 146.65,12.98 128.13,31.5 v1(94.49,31.5)
HOU: R12.1 U1.15 | length 1335.2
  Top Layer w9.84: v1(-665.35,-259.84) v1(-665.35,-283.46) -665.35,-367.34 -633.86,-398.83 -633.86,-479.48 -607.44,-505.91 U1.15@-566.93,-505.91
  Bottom Layer w9.84: R12.1@-850.39,413.39 -1019.69,244.09 -1019.69,-94.77 -866.42,-248.03 -677.17,-248.03 v1(-665.35,-259.84)
  Bottom Layer w23.62: v1(-665.35,-283.46) v1(-665.35,-259.84)
HOV: R13.1 U1.10 | length 1554
  Top Layer w9.84: v1@-496.06,-259.84 -500.98,-264.76 -500.98,-346.3 -474.41,-372.88 U1.10@-474.41,-413.39
  Bottom Layer w9.84: R13.1@-559.06,413.39 -582.68,389.76 -582.68,291.34 -614.17,259.84 -897.92,259.84 -964.57,193.19 -964.57,-75.08 -846.74,-192.91 -566.93,-192.91 v1(-500,-259.84)
  Bottom Layer w23.62: v1(-500,-283.46) v1(-500,-259.84)
HOW: R14.1 U1.4 | length 1880.6
  Top Layer w9.84: U1.4@-356.3,-413.39 -356.3,-371.41 -334.65,-349.76 v1(-334.65,-283.46) v1(-334.65,-259.84)
  Bottom Layer w9.84: v1@-334.65,-263.78 -456.69,-141.73 -819.18,-141.73 -905.51,-55.4 -905.51,173.51 -871.34,207.68 -339.57,207.68 -291.34,255.91 -291.34,397.64 R14.1@-275.59,413.39
  Bottom Layer w23.62: v1(-334.65,-283.46) v1@-334.65,-263.78
HV: BR1.1 C1.1 C2.1 Q1.2 Q2.2 Q3.2 R1.2 R27.2 TP1.1 U3.5 U3.6 | length 89.1
  Bottom Layer w78.74: Q3.2@-208.66,118.11 Q3.2@-145.67,55.12
I_U: Q4.3 R3.1 R21.1 RS1.2 | length 1271.2
  Top Layer w9.84: -909.45,137.8 -822.83,137.8 -807.09,122.05 -807.09,3.94 -751.97,-51.18 -358.55,-51.18 -130.2,-279.53 v1(74.8,-279.53)
  Bottom Layer w9.84: v1(74.8,-279.53) 74.8,-283.46 78.74,-287.4 R3.1@78.74,-322.83
I_V: Q5.3 R6.1 R32.1 RS2.2 | length 979.6
  Top Layer w9.84: RS2.2@-425.19,137.8 RS2.2@-413.38,137.8 -374.02,137.8 -358.27,122.05 -358.27,90.83 -118.11,-149.33 -118.11,-149.61 -32.48,-235.24 101.1,-235.24 142.72,-276.85 142.72,-424.21 v1(118.11,-448.82)
  Bottom Layer w9.84: R32.1@78.74,-448.82 v1(118.11,-448.82)
LEDA: LED.4 U1.30 | length 325.3
  Top Layer w9.84: LED.4@-435.68,-1044.06 -404.49,-1012.86 -404.49,-970.72 -404.53,-970.68 -404.53,-926.96 -404.49,-926.91 -404.49,-899.86 -404.53,-899.82 -404.53,-894.68 -415.35,-883.86 U1.30@-415.35,-736.22
LEDB: J_TX.2 LED.3 U1.28 | length 708.4
  Top Layer w9.84: J_TX.2@-629.92,-720.47 -612.2,-702.76 -532.35,-702.76 -521.53,-691.93 -466.66,-691.93 -454.72,-703.87 U1.28@-454.72,-736.22 -454.72,-819.67 -495.08,-860.03 -495.08,-975.75 -473.44,-997.39 -473.44,-1065.65 -472.81,-1066.28 -472.81,-1066.39 -452.62,-1086.57 -452.52,-1086.57 -452.48,-1086.61 -379.02,-1086.61 LED.3@-360.8,-1068.39
LEDC: LED.2 U1.23 | length 813.9
  Top Layer w9.84: U1.23@-566.93,-663.39 -513.78,-663.39 v1(-511.81,-665.35) ; v1(-505.91,-808.07) -552.5,-808.07 -591.54,-847.11 -591.54,-998.21 -526.76,-1062.99 -503.94,-1062.99 -492.5,-1074.43 -492.5,-1074.54 -460.78,-1106.26 -460.67,-1106.26 -456.03,-1110.9 -304.09,-1110.9 LED.2@-285.91,-1092.72
  Bottom Layer w9.84: v1(-511.81,-665.35) -511.81,-802.17 v1(-505.91,-808.07)
LOU: R18.1 U1.48 | length 1269.7
  Top Layer w9.84: R18.1@-1043.31,122.05 -850.39,-70.87 -366.7,-70.87 -184.05,-253.51 -184.05,-435.46 -215.13,-466.54 U1.48@-244.09,-466.54
LOV: R19.1 U1.47 | length 1012.1
  Top Layer w9.84: R19.1@-610.24,122.05 -535.43,47.24 -342.52,47.24 -137.8,-157.48 -137.8,-157.76 -102.36,-193.19 v1(-102.36,-216.54) ; U1.47@-244.09,-486.22 -206.97,-486.22 -164.37,-443.62 -164.37,-306.1 v1(-157.48,-299.21)
  Bottom Layer w9.84: v1(-157.48,-299.21) -157.48,-271.65 v1(-102.36,-216.54)
LOW: R5.1 U1.46 | length 864.9
  Top Layer w9.84: U1.46@-244.09,-505.91 -198.82,-505.91 -144.68,-451.77 -144.68,-325.79 v1(-129.92,-311.02) ; R5.1@-177.17,122.05 3.94,-59.06 v1(3.94,-185.04)
  Bottom Layer w9.84: v1(-129.92,-311.02) -129.92,-286.77 -67.56,-224.41 -11.81,-224.41 3.94,-208.66 v1(3.94,-185.04)
MU: C16.2 Q1.3 Q4.2 R15.1 U1.14 U.1 | length 1465.7
  Top Layer w9.84: C16.2@-629.92,-330.71 -614.17,-346.46 -614.17,-471.33 -599.28,-486.22 U1.14@-566.93,-486.22 ; C16.2@-629.92,-314.96 C16.2@-622.05,-322.83
  Top Layer w23.62: C16.2@-629.92,-314.96 v1(-629.92,-283.46) v1(-629.92,-259.84)
  Bottom Layer w9.84: -807.09,500 -815.94,491.14 -815.94,392.2 -828.53,379.61 -828.53,378.94 -857,378.94 -1000,235.94 -1000,-86.61 -858.27,-228.35 -649.61,-228.35 -629.92,-248.03 v1(-629.92,-259.84) ; Q1.3@-659.45,320.87 Q1.3@-659.45,340.55 ; Q1.3@-655.51,297.24 Q1.3@-655.51,320.87
  Bottom Layer w23.62: v1(-629.92,-283.46) v1(-629.92,-259.84)
  other v1: -1062.99,472.44 -1015.75,472.44 -968.5,472.44 -1110.24,511.81 -1062.99,511.81 -1015.75,511.81 -968.5,511.81 -921.26,511.81 -874.02,511.81 -826.77,511.81 -779.53,511.81 -732.28,511.81 -1062.99,551.18 -1015.75,551.18 -968.5,551.18 -921.26,551.18 -874.02,551.18 -826.77,551.18 -779.53,551.18 -732.28,551.18 -1062.99,590.55 -1015.75,590.55 -968.5,590.55 -921.26,590.55 -874.02,590.55 -826.77,590.55 -779.53,590.55 -732.28,590.55 -1015.75,629.92 -968.5,629.92 -921.26,629.92 -874.02,629.92 -826.77,629.92 -779.53,629.92 -732.28,629.92
MV: C19.2 Q2.3 Q5.2 R16.1 U1.9 V.1 | length 1649
  Top Layer w9.84: C19.2@-468.5,-334.65 -454.72,-348.43 U1.9@-454.72,-413.39 ; C19.2@-460.63,-318.9 C19.2@-456.69,-322.83
  Top Layer w23.62: C19.2@-460.63,-318.9 v1(-460.63,-283.46) v1(-460.63,-259.84)
  Bottom Layer w9.84: v1(-460.63,-259.84) -547.24,-173.23 -838.58,-173.23 -944.88,-66.93 -944.88,185.04 -889.76,240.16 -402.56,240.16 -368.11,274.61 Q2.3@-368.11,320.87
  Bottom Layer w23.62: v1(-460.63,-283.46) v1(-460.63,-259.84)
  other v1: -539.37,511.81 -492.13,511.81 -444.88,511.81 -586.61,551.18 -539.37,551.18 -492.13,551.18 -444.88,551.18 -633.86,590.55 -586.61,590.55 -539.37,590.55 -492.13,590.55 -444.88,590.55 -633.86,629.92 -586.61,629.92 -539.37,629.92 -492.13,629.92 -444.88,629.92 -633.86,669.29 -594.49,669.29 -633.86,708.66 -594.49,708.66 -830.71,748.03 -791.34,748.03 -751.97,748.03 -712.6,748.03 -673.23,748.03 -633.86,748.03 -791.34,787.4 -751.97,787.4 -712.6,787.4 -673.23,787.4 -633.86,787.4
MW: C21.2 Q3.3 Q6.2 R17.1 U1.3 W.1 | length 1985.4
  Top Layer w9.84: U1.3@-336.61,-413.39 -336.61,-379.57 -311.02,-353.98 -311.02,-346.46 -299.21,-334.65 C21.2@-299.21,-322.83 ; C21.2@-295.28,-318.9 C21.2@-291.34,-322.83
  Top Layer w23.62: C21.2@-295.28,-318.9 v1(-295.28,-283.46) v1(-295.28,-259.84)
  Bottom Layer w9.84: v1@-295.28,-267.72 -295.28,-261.63 -434.86,-122.05 -811.02,-122.05 -885.83,-47.24 -885.83,165.35 -863.19,187.99 -186.02,187.99 -80.71,293.31 Q3.3@-80.71,320.87 Q3.3@-91.54,331.69
  Bottom Layer w23.62: v1(-295.28,-283.46) v1@-295.28,-267.72
  other v1: -254.58,511.81 -207.33,511.81 -160.09,511.81 -301.82,551.18 -254.58,551.18 -207.33,551.18 -160.09,551.18 -349.06,590.55 -301.82,590.55 -254.58,590.55 -207.33,590.55 -160.09,590.55 -349.06,629.92 -301.82,629.92 -254.58,629.92 -207.33,629.92 -160.09,629.92 -349.06,669.29 -309.69,669.29 -270.32,669.29 -230.95,669.29 -191.58,669.29 -349.06,708.66 -309.69,708.66 -270.32,708.66 -230.95,708.66 -349.06,748.03 -309.69,748.03 -270.32,748.03 -388.43,787.4 -349.06,787.4 -309.69,787.4 -427.8,826.77 -388.43,826.77 -349.06,826.77 -467.17,866.14 -427.8,866.14 -388.43,866.14 -507.87,870.08 -624.65,905.51 -585.28,905.51 -545.91,905.51 -506.54,905.51 -467.17,905.51 -427.8,905.51 -507.87,937.01 -624.65,944.88 -585.28,944.88 -545.91,944.88
NetBR1_2: BR1.2 CM1.3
